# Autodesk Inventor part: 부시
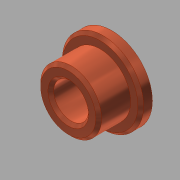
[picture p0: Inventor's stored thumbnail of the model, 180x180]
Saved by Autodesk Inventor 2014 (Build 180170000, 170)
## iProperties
Created: 2016-02
Part Number: 부시
Material: 강철, 연강
Document SubType Name: Modeling
Designer: test
Density: 1 g/cm^3
Appearance: Metal 1400F Hot
Author: test
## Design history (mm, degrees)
sketch "스케치1"
  geometry: C1 r 14 at (0, 0); C2 r 10.5 at (0, 0); 1 further point
  constraints: 2 centre point, 2 coincident
  dimensions: "d0" = 28 diameter of C1; "d1" = 21 diameter of C2
extrude "돌출1" new body sketch "스케치1" distance "d2" = 4; taper "d3" = 0 deg
extrude "돌출2" join sketch "스케치1" distance "d4" = 11; taper "d5" = 0 deg
hole "구멍1" diameter "d8" = 12; stored, may be unused: countersink angle "d12" = 90 deg, drill point angle "d14" = 118 deg; dims "d6" = 10, "d7" = 10, "d9" = 6, "d10" = 4, "d11" = 2, "d13" = 8
chamfer "모따기1" distance "d15" = 1; stored, may be unused: second distance "d16" = 2, angle "d17" = 45 deg
chamfer "모따기2" distance "d18" = 1; stored, may be unused: second distance "d19" = 2, angle "d20" = 45 deg
node "솔리드1"
